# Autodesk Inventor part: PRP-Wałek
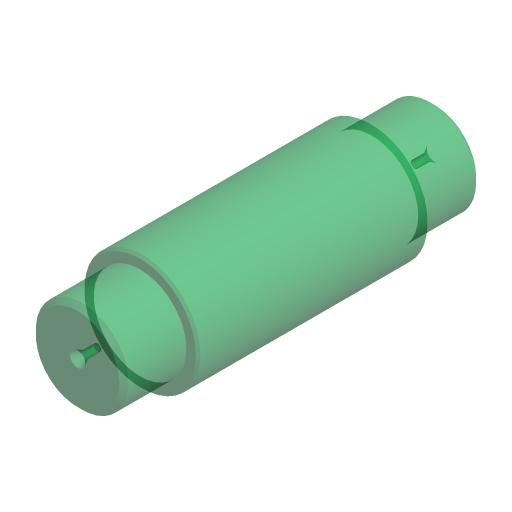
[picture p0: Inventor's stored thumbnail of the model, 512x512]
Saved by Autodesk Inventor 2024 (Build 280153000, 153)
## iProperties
Created: 2023-03
Part Number: PRP-Wałek
Document SubType Name: Modeling
Designer: Andrzej Jaskulski
Material: Kurs-AJ
Density: 1 g/cm^3
Mass: 32.9189 g
Surface Area: 65.2455 cm^2
Volume: 32.9189 cm^3
Appearance: Przezroczyste - zielone 1
Checked By: A.J.
Engr Approved By: Andrzej Jaskulski
Mfg Approved By: Andrzej Jaskulski
Authority: A.J.
Company: ATC
Control State: 0
Master: False
Checked Out: False
Shininess: 20.0
Length Units: 11269
Angle Units: 11279
Time Units: 11290
Mass Units: 11283
Length Display Precision: 3
Angle Display Precision: 2
Compacted: True
Density: 0.0
Volumn: 0.0
Area: 0.0
PropertySet Name: Model Information
Title: A.J.: Kurs R2024-MEP
Author: Andrzej Jaskulski
Revision Number: 1/24
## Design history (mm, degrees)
workplane "Work Plane2"
node "Hole1" dims "d9" = 1.6, "d10" = 3.35, "d11" = 2, "d12" = 60 deg, "d13" = 4.3, "d14" = 120 deg, "d30" = 6
node "Mirror1"
node "Chamfer1" dims "d15" = 1, "d16" = 1, "d31" = 45 deg
node "Chamfer2" dims "d17" = 0.5, "d18" = 0.5, "d32" = 45 deg
node "Bryła1"
  node "Extrusion1" dims "d1" = 50, "d2" = 0
  node "Extrusion2" dims "d5" = 13.5, "d6" = 0
workaxis "Work Axis1"
node "Korpusy bryłowe"
node "Korpusy powierzchniowe"
sketch "Sketch1"
  geometry: C1 r 12.5 at (0, 0)
  constraints: 1 centre point
  dimensions: "d3" = 25 diameter of C1
sketch "Sketch2"
  geometry: C1 r 12.5 at (0, 0) reference; C2 r 10 at (0, 0)
  constraints: 1 centre point, 1 coincident
  dimensions: "d4" = 20 diameter of C2
sketch "Sketch3"
  geometry: C1 r 10 at (0, 0) reference; 1 further point
  constraints: 1 coincident
other parameters: "d8" = -25, "d24" = 45 (derived)
